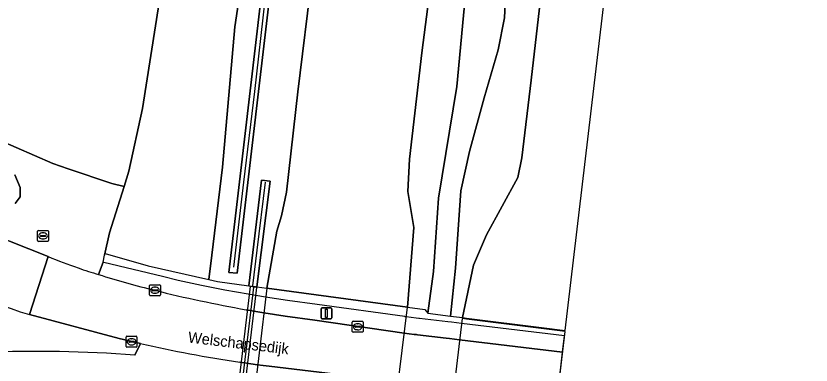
# Model space of a CAD drawing. Extents: x 156061 to 157804, y 383437 to 385640.
# Drawn here: x 157701.1 to 157774.1, y 383655.1 to 383687.1 of the extents above; entities that cross this region are included whole.
import ezdxf

# ---------------------------------------------------------------- set-up
doc = ezdxf.new("R2010")
doc.units = 0
for name, color, linetype in [('IMGEO_Berm_groen', 7, 'Continuous'), ('IMGEO_Fietspad_gesloten', 7, 'Continuous'), ('IMGEO_Geluidsscherm', 7, 'Continuous'), ('IMGEO_Grasland_overig', 7, 'Continuous'), ('IMGEO_Groenvoorziening', 7, 'Continuous'), ('IMGEO_Kolk', 7, 'Continuous'), ('IMGEO_Lichtmast', 7, 'Continuous'), ('IMGEO_Muur', 7, 'Continuous'), ('IMGEO_Openbare_ruimte_label', 7, 'Continuous'), ('IMGEO_Rijbaan_autosnelweg', 7, 'Continuous'), ('IMGEO_Rijbaan_autoweg', 7, 'Continuous'), ('IMGEO_Rijbaan_lokaal_gesloten', 7, 'Continuous'), ('IMGEO_Rijbaan_lokaal_open', 7, 'Continuous'), ('IMGEO_Rioolput', 7, 'Continuous'), ('IMGEO_Voetpad_gesloten', 7, 'Continuous')]:
    doc.layers.add(name, color=color, linetype=linetype)

msp = doc.modelspace()

# ---------------------------------------------------------------- linework, layer by layer
at = {"layer": 'IMGEO_Berm_groen'}
for points in [[(157746.4, 383750.061), (157745.117, 383738.448), (157743.7, 383727.433), (157741.843, 383712.697), (157740.58, 383700.758), (157738.386, 383683.711), (157737.249, 383673.97), (157737.079, 383671.011), (157737.637, 383667.683), (157737.057, 383660.4), (157738.654, 383660.185), (157738.92, 383659.835), (157739.44, 383663.652), (157739.912, 383670.397), (157741.598, 383680.641), (157742.806, 383693.693), (157743.869, 383704.059), (157744.981, 383712.874), (157746.845, 383725.741), (157747.943, 383737.666), (157750.001, 383751.204)], [(157752.067, 383741.672), (157750.77, 383729.946), (157749.277, 383715.662), (157748.82, 383712.6), (157747.119, 383704.397), (157746.721, 383701.514), (157746.347, 383695.523), (157745.955, 383686.927), (157745.391, 383683.98), (157744.104, 383679.597), (157742.747, 383674.668), (157741.95, 383671.056), (157741.473, 383663.974), (157741.005, 383659.578), (157742.101, 383659.442), (157743.111, 383664.24), (157744.3, 383667.036), (157747.198, 383672.277), (157747.549, 383674.09), (157748.398, 383681.217), (157749.445, 383690.253), (157750.61, 383699.987), (157751.82, 383712.586), (157755.872, 383746)], [(157723.015, 383698.147), (157721.228, 383686.096), (157720.092, 383673.241), (157719.108, 383665.149), (157718.842, 383662.923), (157719.638, 383662.743), (157722.502, 383662.358), (157723.664, 383672.04), (157724.445, 383671.962), (157723.243, 383662.258), (157724.148, 383662.136), (157725.067, 383667.364), (157725.492, 383668.778), (157725.95, 383670.924), (157726.998, 383680.128), (157728.307, 383690.881)], [(157724.367, 383688.49), (157723.382, 383680.178), (157722.419, 383671.81), (157721.435, 383663.498), (157720.663, 383663.576), (157721.629, 383671.888), (157722.621, 383680.238), (157723.594, 383688.606)]]:
    msp.add_lwpolyline(points, dxfattribs=at)
at = {"layer": 'IMGEO_Fietspad_gesloten'}
for points in [[(157712.545, 383657.066), (157712.033, 383655.999)], [(157750.298, 383647.882), (157750.722, 383651.464), (157750.722, 383651.464), (157741.268, 383652.581), (157740.346, 383652.69), (157740.027, 383652.728), (157737.428, 383653.035), (157737.228, 383653.059), (157737.07, 383653.077), (157736.174, 383653.183), (157735.925, 383653.213), (157735.814, 383653.226), (157735.848, 383653.589), (157724.374, 383654.964), (157723.828, 383655.035), (157723.281, 383655.108), (157721.661, 383655.34)]]:
    msp.add_lwpolyline(points, dxfattribs=at)
for centre, radius, start, end in [((157739.724, 383775.677), 121.685, 257.09387, 261.46349), ((157703.219, 383539.719), 116.614, 85.66523, 92.46128)]:
    msp.add_arc(centre, radius, start, end, dxfattribs=at)
at = {"layer": 'IMGEO_Geluidsscherm'}
for points in [[(157726.919, 383713.541), (157725.935, 383705.238), (157725.006, 383696.937), (157723.968, 383688.557), (157723.006, 383680.18), (157722.022, 383671.858), (157721.109, 383664.045)], [(157722.865, 383662.353), (157723.252, 383665.627), (157724.016, 383671.87)], [(157721.564, 383650.473), (157722.952, 383662.235)]]:
    msp.add_lwpolyline(points, dxfattribs=at)
at = {"layer": 'IMGEO_Grasland_overig'}
msp.add_lwpolyline([(157750.001, 383751.204), (157747.943, 383737.666), (157746.845, 383725.741), (157744.981, 383712.874), (157743.869, 383704.059), (157742.806, 383693.693), (157741.598, 383680.641), (157739.912, 383670.397), (157739.44, 383663.652), (157738.92, 383659.835), (157741.005, 383659.578), (157741.473, 383663.974), (157741.95, 383671.056), (157742.747, 383674.668), (157744.104, 383679.597), (157745.391, 383683.98), (157745.955, 383686.927), (157746.347, 383695.523), (157746.721, 383701.514), (157747.119, 383704.397), (157748.82, 383712.6), (157749.277, 383715.662), (157750.77, 383729.946), (157752.067, 383741.672)], dxfattribs=at)
msp.add_lwpolyline([(157718.842, 383662.923), (157719.108, 383665.149), (157720.092, 383673.241), (157721.228, 383686.096), (157723.015, 383698.147), (157724.798, 383710.705), (157725.901, 383723.023), (157726.484, 383733.729), (157724.12, 383734.265), (157720.251, 383734.722), (157719.96, 383734.77), (157716.905, 383709.876), (157715.413, 383698.94), (157714.298, 383688.44), (157714.286, 383688.328), (157712.741, 383678.602), (157711.491, 383672.869), (157711.048, 383671.456), (157709.713, 383667.202), (157709.269, 383665.15), (157709.322, 383665.321), (157713.264, 383664.187)], close=True, dxfattribs=at)
at = {"layer": 'IMGEO_Groenvoorziening'}
msp.add_lwpolyline([(157714.298, 383688.44), (157709.892, 383688.845), (157708.841, 383687.969), (157707.48, 383687.939), (157706.62, 383688.65), (157706.133, 383690.186), (157706.057, 383693.589), (157706.886, 383700.855), (157705.493, 383699.687), (157702.391, 383696.169), (157700.096, 383693.247), (157696.374, 383687.785), (157691.823, 383679.959), (157693.506, 383678.954), (157696.299, 383677.426), (157699.436, 383675.782), (157704.517, 383673.556), (157705.926, 383673.079), (157709.923, 383671.727), (157711.048, 383671.456), (157711.491, 383672.869), (157712.741, 383678.602), (157714.286, 383688.328)], close=True, dxfattribs=at)
for points in [[(157708.714, 383663.383), (157709.13, 383664.506), (157709.131, 383664.512), (157709.269, 383665.15), (157709.713, 383667.202), (157711.048, 383671.456), (157709.923, 383671.727), (157705.926, 383673.079), (157704.517, 383673.556), (157699.436, 383675.782)], [(157701.064, 383669.904), (157701.527, 383670.503), (157701.525, 383671.353), (157701.039, 383672.543)], [(157701.039, 383672.543), (157701.525, 383671.353), (157701.527, 383670.503), (157701.064, 383669.904)], [(157700.386, 383666.519), (157700.544, 383666.456), (157704.092, 383665.041)], [(157712.033, 383655.999), (157712.545, 383657.066), (157710.603, 383657.507), (157702.389, 383659.704)]]:
    msp.add_lwpolyline(points, dxfattribs=at)
for centre, radius, start, end in [((157736.579, 383769.162), 114.673, 245.47521, 252.6532), ((157721.196, 383705.446), 43.876, 247.05673, 250.90179), ((157721.965, 383707.851), 46.4, 250.97565, 253.40636), ((157703.219, 383539.719), 116.614, 85.66523, 92.46128)]:
    msp.add_arc(centre, radius, start, end, dxfattribs=at)
at = {"layer": 'IMGEO_Kolk'}
for p, q in [((157713.382, 383661.514), (157713.382, 383662.366)), ((157713.457, 383662.44), (157714.309, 383662.44)), ((157714.383, 383662.366), (157714.383, 383661.514)), ((157713.641, 383661.934), (157713.641, 383661.946)), ((157714.079, 383661.897), (157713.681, 383661.897)), ((157713.684, 383661.983), (157714.082, 383661.983)), ((157713.893, 383661.66), (157713.868, 383661.66)), ((157713.87, 383662.22), (157713.895, 383662.22)), ((157714.125, 383661.946), (157714.125, 383661.934)), ((157714.309, 383661.44), (157713.457, 383661.44)), ((157731.996, 383658.17), (157731.996, 383659.022)), ((157732.071, 383659.096), (157732.923, 383659.096)), ((157732.484, 383658.876), (157732.509, 383658.876)), ((157732.997, 383659.022), (157732.997, 383658.17)), ((157732.923, 383658.096), (157732.071, 383658.096)), ((157732.255, 383658.59), (157732.255, 383658.602)), ((157732.693, 383658.553), (157732.295, 383658.553)), ((157732.298, 383658.639), (157732.696, 383658.639)), ((157732.507, 383658.316), (157732.482, 383658.316)), ((157732.739, 383658.602), (157732.739, 383658.59)), ((157711.237, 383656.791), (157711.237, 383657.643)), ((157711.312, 383657.717), (157712.164, 383657.717)), ((157711.496, 383657.211), (157711.496, 383657.223)), ((157711.539, 383657.26), (157711.937, 383657.26)), ((157711.725, 383657.497), (157711.75, 383657.497)), ((157711.98, 383657.223), (157711.98, 383657.211)), ((157712.238, 383657.643), (157712.238, 383656.791)), ((157712.164, 383656.717), (157711.312, 383656.717)), ((157711.934, 383657.174), (157711.536, 383657.174)), ((157711.748, 383656.937), (157711.723, 383656.937))]:
    msp.add_line(p, q, dxfattribs=at)
for points in [[(157713.382, 383661.514), (157713.382, 383662.366)], [(157713.457, 383662.44), (157714.309, 383662.44)], [(157714.383, 383662.366), (157714.383, 383661.514)], [(157714.309, 383661.44), (157713.457, 383661.44)], [(157731.996, 383658.17), (157731.996, 383659.022)], [(157732.071, 383659.096), (157732.923, 383659.096)], [(157732.997, 383659.022), (157732.997, 383658.17)], [(157732.923, 383658.096), (157732.071, 383658.096)], [(157711.237, 383656.791), (157711.237, 383657.643)], [(157711.312, 383657.717), (157712.164, 383657.717)], [(157712.238, 383657.643), (157712.238, 383656.791)], [(157712.164, 383656.717), (157711.312, 383656.717)]]:
    msp.add_lwpolyline(points, dxfattribs=at)
for centre, radius, start, end in [((157713.459, 383662.364), 0.0765, 91.55205, 178.44795), ((157713.459, 383662.364), 0.0765, 91.55205, 178.44795), ((157714.307, 383662.364), 0.0765, 1.55205, 88.44795), ((157714.307, 383662.364), 0.0765, 1.55205, 88.44795), ((157713.681, 383661.943), 0.0403, 85.87752, 175.75265), ((157713.678, 383661.933), 0.0366, 178.93798, 274.71019), ((157714.082, 383661.94), 0.043, 264.86636, 352.45326), ((157714.086, 383661.945), 0.0386, 1.73085, 96.63898), ((157713.459, 383661.516), 0.0765, 181.55205, 268.44795), ((157713.459, 383661.516), 0.0765, 181.55205, 268.44795), ((157714.307, 383661.516), 0.0765, 271.55205, 358.44795), ((157714.307, 383661.516), 0.0765, 271.55205, 358.44795), ((157732.073, 383659.02), 0.0765, 91.55205, 178.44795), ((157732.073, 383659.02), 0.0765, 91.55205, 178.44795), ((157732.921, 383659.02), 0.0765, 1.55205, 88.44795), ((157732.921, 383659.02), 0.0765, 1.55205, 88.44795), ((157732.073, 383658.172), 0.0765, 181.55205, 268.44795), ((157732.073, 383658.172), 0.0765, 181.55205, 268.44795), ((157732.295, 383658.599), 0.0403, 85.87752, 175.75265), ((157732.292, 383658.589), 0.0366, 178.93798, 274.71019), ((157732.696, 383658.596), 0.043, 264.86636, 352.45326), ((157732.7, 383658.601), 0.0386, 1.73085, 96.63898), ((157732.921, 383658.172), 0.0765, 271.55205, 358.44795), ((157732.921, 383658.172), 0.0765, 271.55205, 358.44795), ((157711.314, 383657.641), 0.0765, 91.55205, 178.44795), ((157711.314, 383657.641), 0.0765, 91.55205, 178.44795), ((157711.536, 383657.22), 0.0403, 85.87752, 175.75265), ((157711.941, 383657.222), 0.0386, 1.73085, 96.63898), ((157712.162, 383657.641), 0.0765, 1.55205, 88.44795), ((157712.162, 383657.641), 0.0765, 1.55205, 88.44795), ((157711.314, 383656.793), 0.0765, 181.55205, 268.44795), ((157711.314, 383656.793), 0.0765, 181.55205, 268.44795), ((157711.533, 383657.21), 0.0366, 178.93798, 274.71019), ((157711.937, 383657.217), 0.043, 264.86636, 352.45326), ((157712.162, 383656.793), 0.0765, 271.55205, 358.44795), ((157712.162, 383656.793), 0.0765, 271.55205, 358.44795)]:
    msp.add_arc(centre, radius, start, end, dxfattribs=at)
for centre, major_axis, ratio, start_param, end_param in [((157713.869, 383661.94), (-0.387, 0.002), 0.722429, 4.712389, 7.853982), ((157713.894, 383661.94), (-0.39, 0.002), 0.717154, 1.570796, 4.712389), ((157732.483, 383658.596), (-0.387, 0.002), 0.722429, 4.712389, 7.853982), ((157732.508, 383658.596), (-0.39, 0.002), 0.717154, 1.570796, 4.712389), ((157711.724, 383657.217), (-0.387, 0.002), 0.722429, 4.712389, 7.853982), ((157711.749, 383657.217), (-0.39, 0.002), 0.717154, 1.570796, 4.712389)]:
    msp.add_ellipse(centre, major_axis=major_axis, ratio=ratio, start_param=start_param, end_param=end_param, dxfattribs=at)
at = {"layer": 'IMGEO_Lichtmast'}
for p, q in [((157729.124, 383659.426), (157729.124, 383660.226)), ((157729.124, 383660.226), (157729.124, 383659.426)), ((157729.224, 383660.326), (157730.014, 383660.326)), ((157730.014, 383660.326), (157729.224, 383660.326)), ((157730.114, 383660.226), (157730.114, 383659.426)), ((157730.114, 383659.426), (157730.114, 383660.226)), ((157730.014, 383659.326), (157729.224, 383659.326)), ((157729.224, 383659.326), (157730.014, 383659.326))]:
    msp.add_line(p, q, dxfattribs=at)
msp.add_lwpolyline([(157729.544, 383660.201), (157729.694, 383660.201), (157729.694, 383659.451), (157729.544, 383659.451), (157729.544, 383660.201)], dxfattribs=at)
for centre, start, end in [((157729.224, 383660.226), 90, 180), ((157729.224, 383660.226), 90, 180), ((157730.014, 383660.226), 0, 90), ((157730.014, 383660.226), 360, 90), ((157729.224, 383659.426), 180, 270), ((157729.224, 383659.426), 180, 270), ((157730.014, 383659.426), 270, 0), ((157730.014, 383659.426), 270, 0)]:
    msp.add_arc(centre, 0.1, start, end, dxfattribs=at)
at = {"layer": 'IMGEO_Muur'}
msp.add_lwpolyline([(157729.524, 383738.631), (157728.911, 383733.515), (157728.526, 383730.306), (157727.529, 383721.972), (157726.545, 383713.548), (157725.542, 383705.268), (157724.587, 383696.938), (157723.594, 383688.606), (157722.621, 383680.238), (157721.629, 383671.888), (157720.663, 383663.576), (157721.435, 383663.498), (157722.419, 383671.81), (157723.382, 383680.178), (157724.367, 383688.49), (157725.36, 383696.812), (157726.351, 383705.181), (157727.348, 383713.523), (157728.335, 383721.884), (157729.316, 383730.199), (157730.276, 383738.549)], dxfattribs=at)
for points in [[(157723.243, 383662.258), (157724.445, 383671.962), (157723.664, 383672.04), (157722.502, 383662.358), (157723.009, 383662.29), (157723.108, 383662.276)], [(157723.231, 383662.206), (157722.615, 383662.278), (157721.225, 383650.504), (157721.841, 383650.431)]]:
    msp.add_lwpolyline(points, close=True, dxfattribs=at)
at = {"layer": 'IMGEO_Rijbaan_autosnelweg'}
msp.add_lwpolyline([(157765.716, 383827.84), (157763.603, 383810.789), (157761.619, 383793.424), (157760.381, 383783.191), (157758.432, 383766.262), (157757.27, 383757.58), (157755.872, 383746), (157751.82, 383712.586), (157750.61, 383699.987), (157749.445, 383690.253), (157748.398, 383681.217), (157747.549, 383674.09), (157747.198, 383672.277), (157744.3, 383667.036), (157743.111, 383664.24), (157742.101, 383659.442), (157742.477, 383659.395), (157749.586, 383658.507), (157751.528, 383658.264), (157774.094, 383848.76)], dxfattribs=at)
msp.add_lwpolyline([(157750.251, 383647.485), (157750.937, 383653.276), (157751.516, 383658.165), (157749.574, 383658.408), (157742.459, 383659.297), (157742.08, 383659.344), (157740.793, 383648.553), (157741.134, 383648.514), (157748.297, 383647.706)], close=True, dxfattribs=at)
at = {"layer": 'IMGEO_Rijbaan_autoweg'}
msp.add_lwpolyline([(157734.396, 383742.421), (157732.786, 383727.807), (157730.885, 383712.196), (157729.521, 383700.57), (157728.307, 383690.881), (157726.998, 383680.128), (157725.95, 383670.924), (157725.492, 383668.778), (157725.067, 383667.364), (157724.148, 383662.136), (157737.057, 383660.4), (157737.637, 383667.683), (157737.079, 383671.011), (157737.249, 383673.97), (157738.386, 383683.711), (157740.58, 383700.758), (157741.843, 383712.697), (157743.7, 383727.433), (157745.117, 383738.448), (157746.4, 383750.061)], dxfattribs=at)
msp.add_lwpolyline([(157737.057, 383660.4), (157724.148, 383662.136), (157722.732, 383650.277), (157735.627, 383648.709)], close=True, dxfattribs=at)
at = {"layer": 'IMGEO_Rijbaan_lokaal_gesloten'}
for points in [[(157704.092, 383665.041), (157702.389, 383659.704), (157710.603, 383657.507), (157712.545, 383657.066)], [(157750.764, 383651.812), (157750.937, 383653.276), (157751.291, 383656.265), (157751.291, 383656.265), (157741.836, 383657.396), (157740.922, 383657.505), (157740.598, 383657.544), (157737.992, 383657.855), (157737.884, 383657.868), (157737.675, 383657.893), (157736.764, 383658.002), (157728.569, 383659.183), (157725.833, 383659.578), (157723.869, 383659.882), (157722.252, 383660.156)], [(157721.661, 383655.34), (157723.281, 383655.108), (157723.828, 383655.035), (157724.374, 383654.964), (157735.848, 383653.589), (157735.975, 383653.574), (157736.218, 383653.545), (157737.116, 383653.438), (157737.277, 383653.419), (157737.47, 383653.396), (157740.07, 383653.086), (157740.388, 383653.048), (157741.31, 383652.938), (157750.763, 383651.812), (157750.764, 383651.812)]]:
    msp.add_lwpolyline(points, dxfattribs=at)
for centre, radius, start, end in [((157721.196, 383705.446), 43.876, 247.05673, 250.90179), ((157721.965, 383707.851), 46.4, 250.97565, 253.40636), ((157729.064, 383726.3), 66.126, 252.07653, 256.7278), ((157743.63, 383780.964), 122.685, 255.96796, 259.96505), ((157739.724, 383775.677), 121.685, 257.09387, 261.46349)]:
    msp.add_arc(centre, radius, start, end, dxfattribs=at)
at = {"layer": 'IMGEO_Rijbaan_lokaal_open'}
msp.add_lwpolyline([(157702.389, 383659.704), (157704.092, 383665.041), (157700.544, 383666.456), (157700.386, 383666.519)], dxfattribs=at)
msp.add_arc((157736.579, 383769.162), 114.673, 245.47521, 252.6532, dxfattribs=at)
at = {"layer": 'IMGEO_Rioolput'}
for p, q in [((157703.115, 383666.501), (157703.115, 383667.353)), ((157703.19, 383667.427), (157704.042, 383667.427)), ((157703.374, 383666.921), (157703.374, 383666.933)), ((157703.812, 383666.884), (157703.414, 383666.884)), ((157703.417, 383666.97), (157703.815, 383666.97)), ((157703.603, 383667.207), (157703.628, 383667.207)), ((157703.858, 383666.933), (157703.858, 383666.921)), ((157704.116, 383667.353), (157704.116, 383666.501)), ((157704.042, 383666.427), (157703.19, 383666.427)), ((157703.626, 383666.647), (157703.601, 383666.647))]:
    msp.add_line(p, q, dxfattribs=at)
for points in [[(157703.115, 383666.501), (157703.115, 383667.353)], [(157703.19, 383667.427), (157704.042, 383667.427)], [(157704.116, 383667.353), (157704.116, 383666.501)], [(157704.042, 383666.427), (157703.19, 383666.427)]]:
    msp.add_lwpolyline(points, dxfattribs=at)
for centre, radius, start, end in [((157703.192, 383667.351), 0.0765, 91.55205, 178.44795), ((157703.192, 383667.351), 0.0765, 91.55205, 178.44795), ((157703.414, 383666.93), 0.0403, 85.87752, 175.75265), ((157703.411, 383666.92), 0.0366, 178.93798, 274.71019), ((157703.815, 383666.927), 0.043, 264.86636, 352.45326), ((157703.819, 383666.932), 0.0386, 1.73085, 96.63898), ((157704.04, 383667.351), 0.0765, 1.55205, 88.44795), ((157704.04, 383667.351), 0.0765, 1.55205, 88.44795), ((157703.192, 383666.503), 0.0765, 181.55205, 268.44795), ((157703.192, 383666.503), 0.0765, 181.55205, 268.44795), ((157704.04, 383666.503), 0.0765, 271.55205, 358.44795), ((157704.04, 383666.503), 0.0765, 271.55205, 358.44795)]:
    msp.add_arc(centre, radius, start, end, dxfattribs=at)
for centre, major_axis, ratio, start_param, end_param in [((157703.602, 383666.927), (-0.387, 0.002), 0.722429, 4.712389, 7.853982), ((157703.627, 383666.927), (-0.39, 0.002), 0.717154, 1.570796, 4.712389)]:
    msp.add_ellipse(centre, major_axis=major_axis, ratio=ratio, start_param=start_param, end_param=end_param, dxfattribs=at)
at = {"layer": 'IMGEO_Voetpad_gesloten'}
for points in [[(157751.291, 383656.265), (157751.468, 383657.757), (157751.467, 383657.757), (157742.013, 383658.894), (157741.101, 383659.003), (157740.775, 383659.042), (157738.167, 383659.356), (157738.088, 383659.365), (157737.863, 383659.392), (157736.947, 383659.502), (157736.858, 383659.513), (157736.802, 383659.521), (157728.773, 383660.629), (157726.043, 383661.006), (157724.045, 383661.302), (157722.425, 383661.567), (157720.286, 383661.954), (157718.155, 383662.379), (157716.031, 383662.844), (157714.567, 383663.189), (157709.185, 383664.493), (157709.13, 383664.506), (157708.714, 383663.383)], [(157722.252, 383660.156), (157723.869, 383659.882), (157725.833, 383659.578), (157728.569, 383659.183), (157736.764, 383658.002), (157737.675, 383657.893), (157737.884, 383657.868), (157737.992, 383657.855), (157740.598, 383657.544), (157740.922, 383657.505), (157741.836, 383657.396), (157751.291, 383656.265), (157751.291, 383656.265)]]:
    msp.add_lwpolyline(points, dxfattribs=at)
for centre, radius, start, end in [((157729.064, 383726.3), 66.126, 252.07653, 256.7278), ((157743.63, 383780.964), 122.685, 255.96796, 259.96505)]:
    msp.add_arc(centre, radius, start, end, dxfattribs=at)

# ---------------------------------------------------------------- texts
at = {"layer": 'IMGEO_Openbare_ruimte_label'}
msp.add_text('Welschapsedijk', height=1, rotation=353.22322, dxfattribs=at).set_placement((157716.88, 383657.155))

doc.saveas('drawing.dxf')
